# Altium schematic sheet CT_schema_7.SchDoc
size 368 x 245 mm
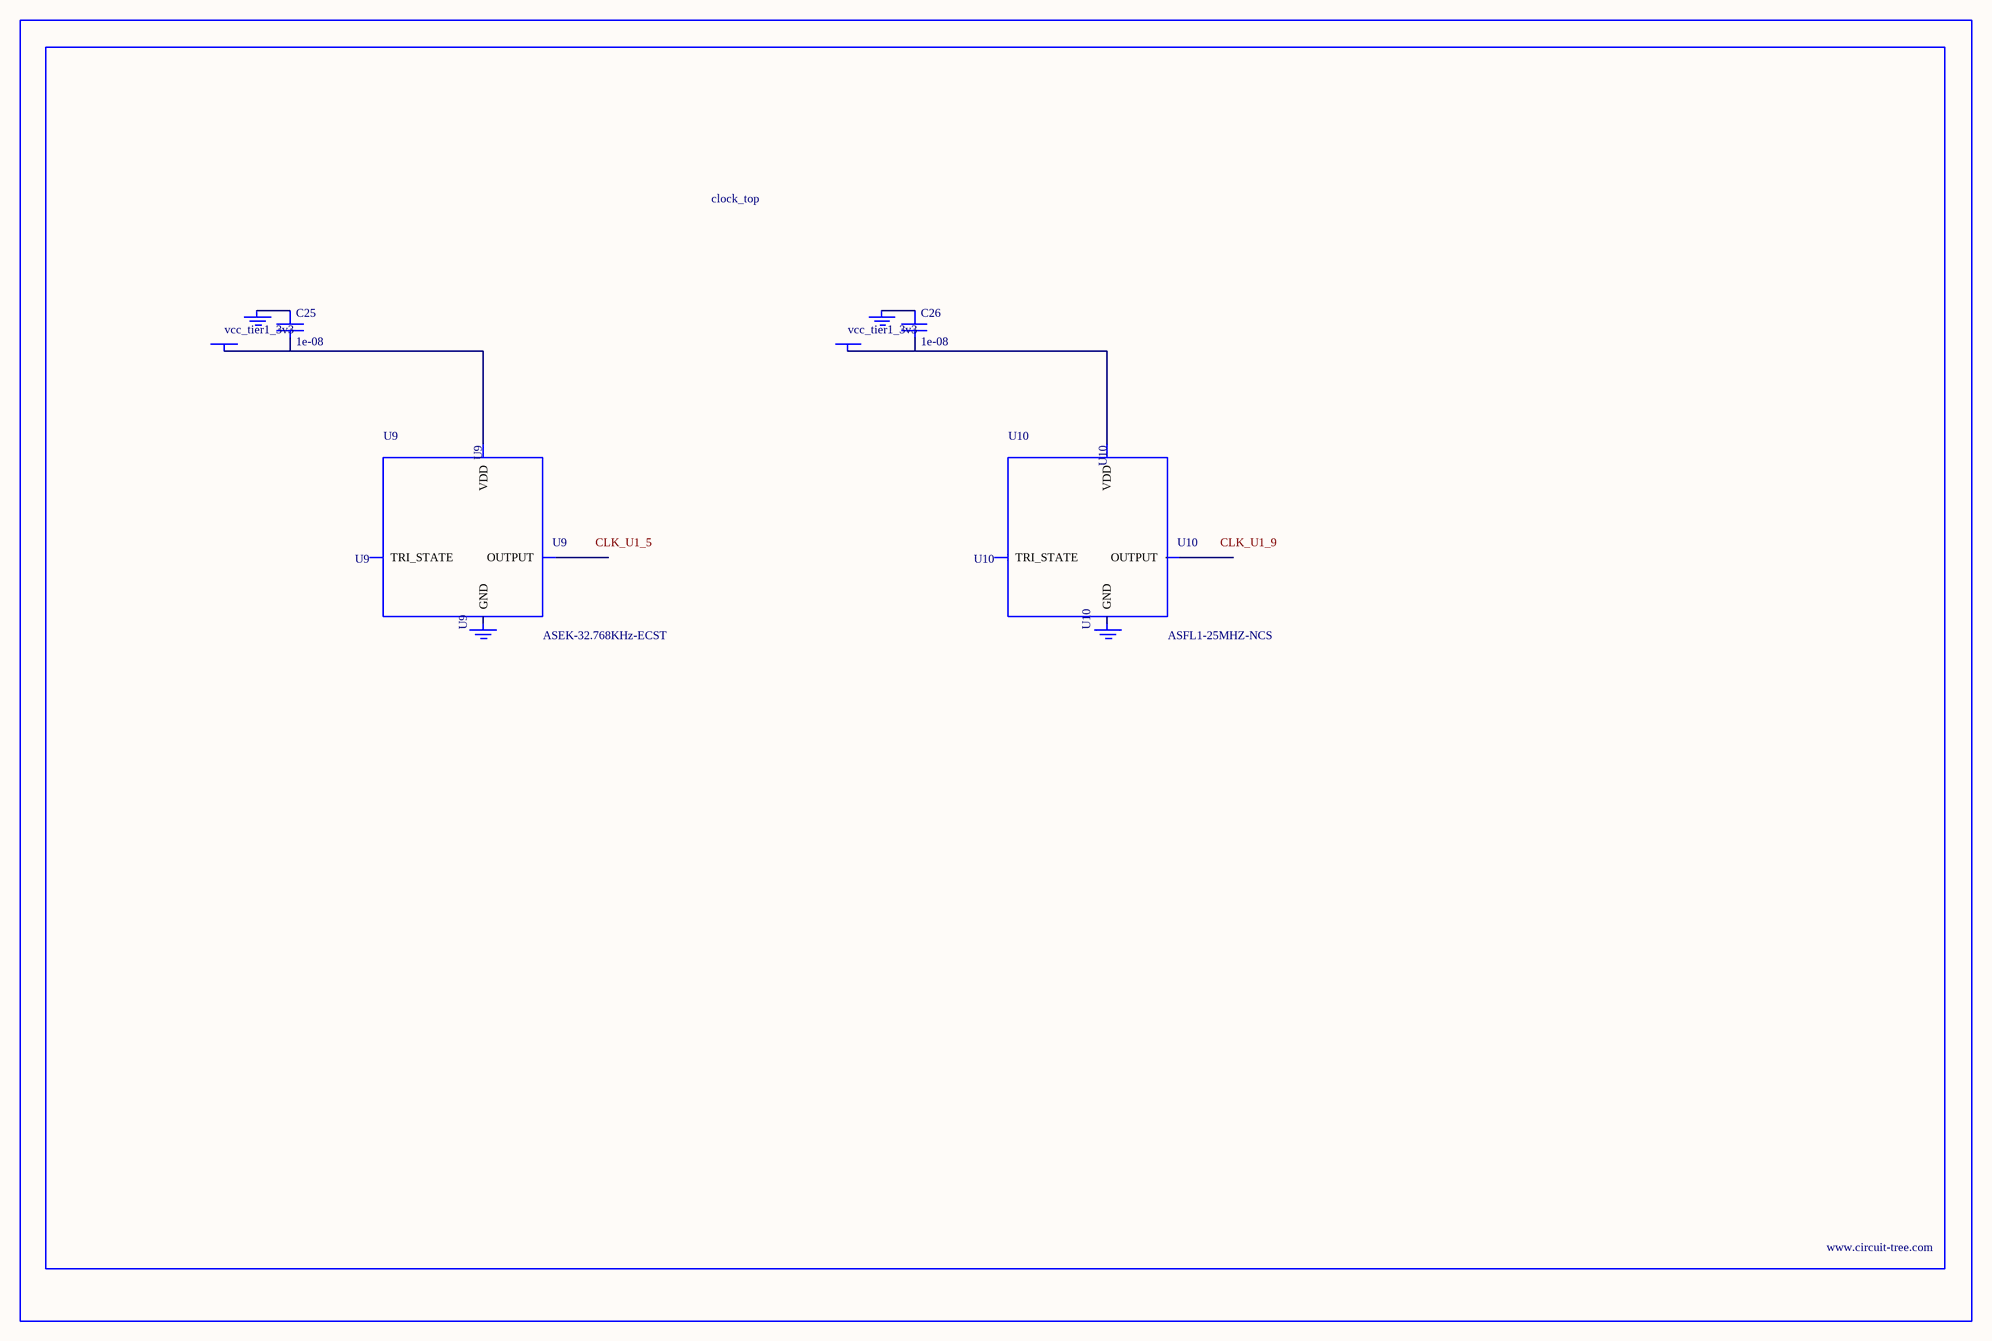
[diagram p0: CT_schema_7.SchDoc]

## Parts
BORDER6  (no value)
C25  1e-08  [C0402]
C26  1e-08  [C0402]
GND_INSTANCE_6_0  (no value)
GND_INSTANCE_6_1  (no value)
GND_INSTANCE_6_2  (no value)
GND_INSTANCE_6_3  (no value)
POWER_INSTANCE_6_0  vcc_tier1_3v3
POWER_INSTANCE_6_1  vcc_tier1_3v3
U9  ASEK-32.768KHz-ECST  [ASEK]
U10  ASFL1-25MHZ-NCS  [ASFL1]

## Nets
NetC25_1: C25.1 GND_INSTANCE_6_0.0(GND)
NetC25_2: C25.2 POWER_INSTANCE_6_0.0(PWR) U9.4(VDD)
NetC26_1: C26.1 GND_INSTANCE_6_2.0(GND)
NetC26_2: C26.2 POWER_INSTANCE_6_1.0(PWR) U10.4(VDD)

Not connected (* = marked no-connect by the designer): GND_INSTANCE_6_1 0(GND); GND_INSTANCE_6_3 0(GND); U9 1(TRI_STATE) 2(GND) 3(OUTPUT); U10 1(TRI_STATE) 2(GND) 3(OUTPUT)

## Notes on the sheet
- Labels drawn without touching a wire or pin: CLK_U1_5, CLK_U1_9

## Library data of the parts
BORDER6 = BORDER_PAGE6
C25 C26 = C0402C103K3RAC
GND_INSTANCE_6_0-GND_INSTANCE_6_3 = GND
POWER_INSTANCE_6_0 POWER_INSTANCE_6_1 = PWR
